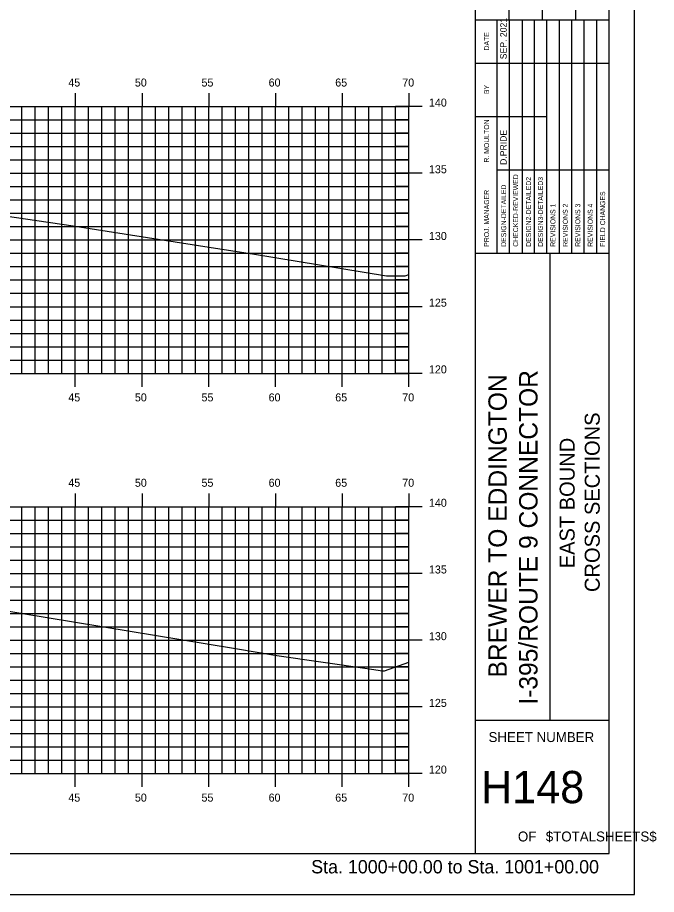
# Model space of a CAD drawing. Extents: x 850630 to 850801, y 365624 to 365734.
# Drawn here: x 850753.4 to 850801.3, y 365624 to 365689.7 of the extents above; entities that cross this region are included whole.
import ezdxf

# ---------------------------------------------------------------- set-up
doc = ezdxf.new("R2010")
doc.units = 0
for name, color, linetype in [('BORDER', 7, 'Continuous'), ('H_V ANNOTATION', 7, 'Continuous'), ('MAJOR', 7, 'Continuous'), ('MINOR', 7, 'Continuous'), ('PLOT BOUNDARY', 7, 'Continuous'), ('S_Roadway_Centerline', 7, 'Continuous')]:
    doc.layers.add(name, color=color, linetype=linetype)

msp = doc.modelspace()

# ---------------------------------------------------------------- linework, layer by layer
at = {"layer": 'BORDER'}
for p, q in [((850787.74, 365627.027), (850787.74, 365732.027)), ((850790.24, 365689.53), (850790.24, 365698.177)), ((850792.74, 365689.53), (850792.74, 365698.177)), ((850795.24, 365689.53), (850795.24, 365698.177)), ((850787.74, 365689.53), (850797.74, 365689.53)), ((850787.74, 365672.03), (850797.74, 365672.03)), ((850793.331, 365637.03), (850793.331, 365672.03)), ((850787.74, 365637.03), (850797.74, 365637.03))]:
    msp.add_line(p, q, dxfattribs=at)
msp.add_lwpolyline([(850637.74, 365627.027), (850797.74, 365627.027), (850797.74, 365732.027), (850637.74, 365732.027)], close=True, dxfattribs=at)
for points in [[(850789.355, 365686.28), (850789.355, 365689.53)], [(850790.287, 365672.033), (850790.287, 365689.53)], [(850791.219, 365689.53), (850791.219, 365672.033)], [(850792.15, 365672.033), (850792.15, 365689.53)], [(850793.082, 365672.033), (850793.082, 365689.53)], [(850794.014, 365672.033), (850794.014, 365689.53)], [(850794.946, 365672.033), (850794.946, 365689.53)], [(850795.877, 365672.033), (850795.877, 365689.53)], [(850796.809, 365672.033), (850796.809, 365689.53)], [(850789.355, 365672.033), (850789.355, 365688.824)], [(850787.74, 365686.28), (850797.74, 365686.28)], [(850787.74, 365682.28), (850789.355, 365682.28)], [(850789.355, 365682.28), (850793.081, 365682.28)], [(850789.355, 365678.28), (850797.74, 365678.28)]]:
    msp.add_lwpolyline(points, dxfattribs=at)
at = {"layer": 'MAJOR'}
for p, q in [((850757.739, 365684.029), (850757.739, 365683.027)), ((850762.739, 365684.029), (850762.739, 365683.027)), ((850767.739, 365684.029), (850767.739, 365683.027)), ((850772.739, 365684.029), (850772.739, 365683.027)), ((850777.739, 365684.029), (850777.739, 365683.027)), ((850782.739, 365684.029), (850782.739, 365683.027)), ((850642.739, 365683.027), (850782.739, 365683.027)), ((850642.739, 365683.027), (850782.739, 365683.027)), ((850757.739, 365663.027), (850757.739, 365683.027)), ((850762.739, 365663.027), (850762.739, 365683.027)), ((850767.739, 365663.027), (850767.739, 365683.027)), ((850772.739, 365663.027), (850772.739, 365683.027)), ((850777.739, 365663.027), (850777.739, 365683.027)), ((850783.741, 365683.027), (850781.737, 365683.027)), ((850782.739, 365663.027), (850782.739, 365683.027)), ((850782.739, 365663.027), (850782.739, 365683.027)), ((850642.739, 365678.027), (850782.739, 365678.027)), ((850783.741, 365678.027), (850781.737, 365678.027)), ((850642.739, 365673.027), (850782.739, 365673.027)), ((850783.741, 365673.027), (850781.737, 365673.027)), ((850642.739, 365668.027), (850782.739, 365668.027)), ((850783.741, 365668.027), (850781.737, 365668.027)), ((850642.739, 365663.027), (850782.739, 365663.027)), ((850642.739, 365663.027), (850782.739, 365663.027)), ((850757.739, 365662.025), (850757.739, 365663.027)), ((850762.739, 365662.025), (850762.739, 365663.027)), ((850767.739, 365662.025), (850767.739, 365663.027)), ((850772.739, 365662.025), (850772.739, 365663.027)), ((850777.739, 365662.025), (850777.739, 365663.027)), ((850783.741, 365663.027), (850781.737, 365663.027)), ((850782.739, 365662.025), (850782.739, 365663.027)), ((850757.739, 365654.029), (850757.739, 365653.027)), ((850762.739, 365654.029), (850762.739, 365653.027)), ((850767.739, 365654.029), (850767.739, 365653.027)), ((850772.739, 365654.029), (850772.739, 365653.027)), ((850777.739, 365654.029), (850777.739, 365653.027)), ((850782.739, 365654.029), (850782.739, 365653.027)), ((850642.739, 365653.027), (850782.739, 365653.027)), ((850642.739, 365653.027), (850782.739, 365653.027)), ((850757.739, 365633.027), (850757.739, 365653.027)), ((850762.739, 365633.027), (850762.739, 365653.027)), ((850767.739, 365633.027), (850767.739, 365653.027)), ((850772.739, 365633.027), (850772.739, 365653.027)), ((850777.739, 365633.027), (850777.739, 365653.027)), ((850783.741, 365653.027), (850781.737, 365653.027)), ((850782.739, 365633.027), (850782.739, 365653.027)), ((850782.739, 365633.027), (850782.739, 365653.027)), ((850642.739, 365648.027), (850782.739, 365648.027)), ((850783.741, 365648.027), (850781.737, 365648.027)), ((850642.739, 365643.027), (850782.739, 365643.027)), ((850783.741, 365643.027), (850781.737, 365643.027)), ((850642.739, 365638.027), (850782.739, 365638.027)), ((850783.741, 365638.027), (850781.737, 365638.027)), ((850642.739, 365633.027), (850782.739, 365633.027)), ((850642.739, 365633.027), (850782.739, 365633.027)), ((850757.739, 365632.025), (850757.739, 365633.027)), ((850762.739, 365632.025), (850762.739, 365633.027)), ((850767.739, 365632.025), (850767.739, 365633.027)), ((850772.739, 365632.025), (850772.739, 365633.027)), ((850777.739, 365632.025), (850777.739, 365633.027)), ((850783.741, 365633.027), (850781.737, 365633.027)), ((850782.739, 365632.025), (850782.739, 365633.027))]:
    msp.add_line(p, q, dxfattribs=at)
at = {"layer": 'MINOR'}
for p, q in [((850753.739, 365663.027), (850753.739, 365683.027)), ((850754.739, 365663.027), (850754.739, 365683.027)), ((850755.739, 365663.027), (850755.739, 365683.027)), ((850756.739, 365663.027), (850756.739, 365683.027)), ((850758.739, 365663.027), (850758.739, 365683.027)), ((850759.739, 365663.027), (850759.739, 365683.027)), ((850760.739, 365663.027), (850760.739, 365683.027)), ((850761.739, 365663.027), (850761.739, 365683.027)), ((850763.739, 365663.027), (850763.739, 365683.027)), ((850764.739, 365663.027), (850764.739, 365683.027)), ((850765.739, 365663.027), (850765.739, 365683.027)), ((850766.739, 365663.027), (850766.739, 365683.027)), ((850768.739, 365663.027), (850768.739, 365683.027)), ((850769.739, 365663.027), (850769.739, 365683.027)), ((850770.739, 365663.027), (850770.739, 365683.027)), ((850771.739, 365663.027), (850771.739, 365683.027)), ((850773.739, 365663.027), (850773.739, 365683.027)), ((850774.739, 365663.027), (850774.739, 365683.027)), ((850775.739, 365663.027), (850775.739, 365683.027)), ((850776.739, 365663.027), (850776.739, 365683.027)), ((850778.739, 365663.027), (850778.739, 365683.027)), ((850779.739, 365663.027), (850779.739, 365683.027)), ((850780.739, 365663.027), (850780.739, 365683.027)), ((850781.739, 365663.027), (850781.739, 365683.027)), ((850642.739, 365682.027), (850782.739, 365682.027)), ((850782.739, 365682.027), (850781.737, 365682.027)), ((850642.739, 365681.027), (850782.739, 365681.027)), ((850782.739, 365681.027), (850781.737, 365681.027)), ((850642.739, 365680.027), (850782.739, 365680.027)), ((850782.739, 365680.027), (850781.737, 365680.027)), ((850642.739, 365679.027), (850782.739, 365679.027)), ((850782.739, 365679.027), (850781.737, 365679.027)), ((850642.739, 365677.027), (850782.739, 365677.027)), ((850782.739, 365677.027), (850781.737, 365677.027)), ((850642.739, 365676.027), (850782.739, 365676.027)), ((850782.739, 365676.027), (850781.737, 365676.027)), ((850642.739, 365675.027), (850782.739, 365675.027)), ((850782.739, 365675.027), (850781.737, 365675.027)), ((850642.739, 365674.027), (850782.739, 365674.027)), ((850782.739, 365674.027), (850781.737, 365674.027)), ((850642.739, 365672.027), (850782.739, 365672.027)), ((850782.739, 365672.027), (850781.737, 365672.027)), ((850642.739, 365671.027), (850782.739, 365671.027)), ((850782.739, 365671.027), (850781.737, 365671.027)), ((850642.739, 365670.027), (850782.739, 365670.027)), ((850782.739, 365670.027), (850781.737, 365670.027)), ((850642.739, 365669.027), (850782.739, 365669.027)), ((850782.739, 365669.027), (850781.737, 365669.027)), ((850642.739, 365667.027), (850782.739, 365667.027)), ((850782.739, 365667.027), (850781.737, 365667.027)), ((850642.739, 365666.027), (850782.739, 365666.027)), ((850782.739, 365666.027), (850781.737, 365666.027)), ((850642.739, 365665.027), (850782.739, 365665.027)), ((850782.739, 365665.027), (850781.737, 365665.027)), ((850642.739, 365664.027), (850782.739, 365664.027)), ((850782.739, 365664.027), (850781.737, 365664.027)), ((850753.739, 365633.027), (850753.739, 365653.027)), ((850754.739, 365633.027), (850754.739, 365653.027)), ((850755.739, 365633.027), (850755.739, 365653.027)), ((850756.739, 365633.027), (850756.739, 365653.027)), ((850758.739, 365633.027), (850758.739, 365653.027)), ((850759.739, 365633.027), (850759.739, 365653.027)), ((850760.739, 365633.027), (850760.739, 365653.027)), ((850761.739, 365633.027), (850761.739, 365653.027)), ((850763.739, 365633.027), (850763.739, 365653.027)), ((850764.739, 365633.027), (850764.739, 365653.027)), ((850765.739, 365633.027), (850765.739, 365653.027)), ((850766.739, 365633.027), (850766.739, 365653.027)), ((850768.739, 365633.027), (850768.739, 365653.027)), ((850769.739, 365633.027), (850769.739, 365653.027)), ((850770.739, 365633.027), (850770.739, 365653.027)), ((850771.739, 365633.027), (850771.739, 365653.027)), ((850773.739, 365633.027), (850773.739, 365653.027)), ((850774.739, 365633.027), (850774.739, 365653.027)), ((850775.739, 365633.027), (850775.739, 365653.027)), ((850776.739, 365633.027), (850776.739, 365653.027)), ((850778.739, 365633.027), (850778.739, 365653.027)), ((850779.739, 365633.027), (850779.739, 365653.027)), ((850780.739, 365633.027), (850780.739, 365653.027)), ((850781.739, 365633.027), (850781.739, 365653.027)), ((850642.739, 365652.027), (850782.739, 365652.027)), ((850782.739, 365652.027), (850781.737, 365652.027)), ((850642.739, 365651.027), (850782.739, 365651.027)), ((850782.739, 365651.027), (850781.737, 365651.027)), ((850642.739, 365650.027), (850782.739, 365650.027)), ((850782.739, 365650.027), (850781.737, 365650.027)), ((850642.739, 365649.027), (850782.739, 365649.027)), ((850782.739, 365649.027), (850781.737, 365649.027)), ((850642.739, 365647.027), (850782.739, 365647.027)), ((850782.739, 365647.027), (850781.737, 365647.027)), ((850642.739, 365646.027), (850782.739, 365646.027)), ((850782.739, 365646.027), (850781.737, 365646.027)), ((850642.739, 365645.027), (850782.739, 365645.027)), ((850782.739, 365645.027), (850781.737, 365645.027)), ((850642.739, 365644.027), (850782.739, 365644.027)), ((850782.739, 365644.027), (850781.737, 365644.027)), ((850642.739, 365642.027), (850782.739, 365642.027)), ((850782.739, 365642.027), (850781.737, 365642.027)), ((850642.739, 365641.027), (850782.739, 365641.027)), ((850782.739, 365641.027), (850781.737, 365641.027)), ((850642.739, 365640.027), (850782.739, 365640.027)), ((850782.739, 365640.027), (850781.737, 365640.027)), ((850642.739, 365639.027), (850782.739, 365639.027)), ((850782.739, 365639.027), (850781.737, 365639.027)), ((850642.739, 365637.027), (850782.739, 365637.027)), ((850782.739, 365637.027), (850781.737, 365637.027)), ((850642.739, 365636.027), (850782.739, 365636.027)), ((850782.739, 365636.027), (850781.737, 365636.027)), ((850642.739, 365635.027), (850782.739, 365635.027)), ((850782.739, 365635.027), (850781.737, 365635.027)), ((850642.739, 365634.027), (850782.739, 365634.027)), ((850782.739, 365634.027), (850781.737, 365634.027))]:
    msp.add_line(p, q, dxfattribs=at)
at = {"layer": 'PLOT BOUNDARY'}
msp.add_lwpolyline([(850629.646, 365623.968), (850799.646, 365623.968), (850799.646, 365733.968), (850629.646, 365733.968)], close=True, dxfattribs=at)
at = {"layer": 'S_Roadway_Centerline'}
for points in [[(850701.203, 365673.361), (850709.069, 365674.533), (850715.031, 365674.764), (850716.605, 365674.827), (850716.849, 365674.849), (850724.444, 365675.377), (850726.057, 365675.398), (850730.303, 365675.565), (850733.164, 365675.676), (850738.143, 365675.748), (850745.83, 365675.875), (850746.894, 365675.65), (850751.259, 365675.008), (850757.573, 365674.085), (850768.246, 365672.41), (850771.008, 365671.981), (850781.056, 365670.333), (850782.47, 365670.35), (850782.739, 365670.436)], [(850703.949, 365644.184), (850704.554, 365644.269), (850708.843, 365644.91), (850717.92, 365645.299), (850721.12, 365645.442), (850724.315, 365645.639), (850724.424, 365645.75), (850728.366, 365645.886), (850733.24, 365646.073), (850737.922, 365646.231), (850740.995, 365646.115), (850747.079, 365646.044), (850749.84, 365645.665), (850769.738, 365642.41), (850772.848, 365641.887), (850779.607, 365640.904), (850780.748, 365640.734), (850780.919, 365640.742), (850782.739, 365641.37)]]:
    msp.add_lwpolyline(points, dxfattribs=at)

# ---------------------------------------------------------------- texts
at = {"layer": 'BORDER'}
for s, height, p in [('SEP. 2021', 0.4845, (850790.063, 365686.575)), ('DATE', 0.3714, (850788.744, 365687.235)), ('BY', 0.3714, (850788.744, 365683.965)), ('R. MOULTON', 0.3727, (850788.744, 365678.832)), ('D.PRIDE', 0.4845, (850790.063, 365678.653)), ('CHECKED-REVIEWED', 0.37275, (850790.921, 365672.518)), ('DESIGN2-DETAILED2', 0.37275, (850791.89, 365672.518)), ('DESIGN3-DETAILED3', 0.37275, (850792.784, 365672.518)), ('DESIGN-DETAILED', 0.37275, (850790.026, 365672.518)), ('PROJ. MANAGER', 0.37275, (850788.744, 365672.518)), ('FIELD CHANGES', 0.37275, (850797.442, 365672.518)), ('REVISIONS 1', 0.37275, (850793.716, 365672.518)), ('REVISIONS 2', 0.37275, (850794.647, 365672.518)), ('REVISIONS 3', 0.37275, (850795.579, 365672.518)), ('REVISIONS 4', 0.37275, (850796.511, 365672.518)), ('I-395/ROUTE 9 CONNECTOR', 1.37787, (850792.375, 365638.192)), ('BREWER TO EDDINGTON', 1.37787, (850790.074, 365640.231)), ('CROSS SECTIONS', 1.125, (850797.037, 365646.638)), ('EAST BOUND', 1.125, (850795.158, 365648.418))]:
    msp.add_text(s, height=height, rotation=90, dxfattribs=at).set_placement(p)
for s, height, p in [('SHEET NUMBER', 0.74527, (850788.705, 365635.393)), ('H148', 2.4194, (850788.141, 365630.809)), ('$TOTALSHEETS$', 0.74527, (850792.996, 365627.94)), ('OF', 0.7453, (850790.907, 365627.94))]:
    msp.add_text(s, height=height, dxfattribs=at).set_placement(p)
at = {"layer": 'H_V ANNOTATION'}
for s, height, p in [('45', 0.6, (850757.218, 365684.527)), ('50', 0.6, (850762.204, 365684.527)), ('55', 0.6, (850767.196, 365684.527)), ('60', 0.6, (850772.226, 365684.527)), ('65', 0.6, (850777.218, 365684.527)), ('70', 0.6, (850782.242, 365684.527)), ('140', 0.6, (850784.239, 365683.027)), ('135', 0.6, (850784.239, 365678.027)), ('130', 0.6, (850784.239, 365673.027)), ('125', 0.6, (850784.239, 365668.027)), ('120', 0.6, (850784.239, 365663.027)), ('45', 0.6, (850757.218, 365660.927)), ('50', 0.6, (850762.204, 365660.927)), ('55', 0.6, (850767.196, 365660.927)), ('60', 0.6, (850772.226, 365660.927)), ('65', 0.6, (850777.218, 365660.927)), ('70', 0.6, (850782.242, 365660.927)), ('45', 0.6, (850757.218, 365654.527)), ('50', 0.6, (850762.204, 365654.527)), ('55', 0.6, (850767.196, 365654.527)), ('60', 0.6, (850772.226, 365654.527)), ('65', 0.6, (850777.218, 365654.527)), ('70', 0.6, (850782.242, 365654.527)), ('140', 0.6, (850784.239, 365653.027)), ('135', 0.6, (850784.239, 365648.027)), ('130', 0.6, (850784.239, 365643.027)), ('125', 0.6, (850784.239, 365638.027)), ('120', 0.6, (850784.239, 365633.027)), ('45', 0.6, (850757.218, 365630.927)), ('50', 0.6, (850762.204, 365630.927)), ('55', 0.6, (850767.196, 365630.927)), ('60', 0.6, (850772.226, 365630.927)), ('65', 0.6, (850777.218, 365630.927)), ('70', 0.6, (850782.242, 365630.927)), ('Sta. 1000+00.00 to Sta. 1001+00.00', 1.0002, (850775.416, 365625.547))]:
    msp.add_text(s, height=height, dxfattribs=at).set_placement(p)

doc.saveas('drawing.dxf')
